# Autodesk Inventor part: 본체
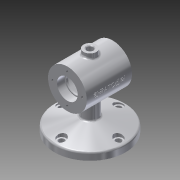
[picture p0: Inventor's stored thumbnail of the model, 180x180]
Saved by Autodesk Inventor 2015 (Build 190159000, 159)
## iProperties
Created: 2018-12
Part Number: 본체
Material: 알루미늄 6061
Document SubType Name: Modeling
Designer: now
Density: 2.7 g/cm^3
Appearance: 알루미늄 - 평지
Mass: 685.366 g
Surface Area: 556.634 cm^2
Volume: 253.839 cm^3
Author: now
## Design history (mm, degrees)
sketch "스케치1"
  geometry: C1 r 55 at (0, 0); 1 further point
  constraints: 1 centre point, 1 coincident
  dimensions: "d0" = 110 diameter of C1
extrude "돌출1" new body sketch "스케치1" distance "d1" = 11; taper "d2" = 0 deg
sketch "스케치2"
  geometry: C1 r 55 at (0, 0) reference; C2 r 12 at (0, 0)
  constraints: 1 centre point, 1 coincident
  dimensions: "d3" = 24 diameter of C2
extrude "돌출2" join sketch "스케치2" distance "d4" = 75; taper "d5" = 0 deg
sketch "스케치3"
  geometry: L1 (-55, 0)-(-55, 11) reference; L2 (-55, 11)-(-12, 11) reference; L3 (-12, 11)-(-12, 86) reference; L4 (-12, 86)-(12, 86) reference; L5 (12, 86)-(12, 11) reference; L6 (12, 11)-(55, 11) reference; L7 (55, 11)-(55, 0) reference; L8 (55, 0)-(-55, 0) reference; L9 (55, 11)-(12, 22.522); L10 (12, 22.522)-(0, 22.522); L11 (0, 22.522)-(0, 11); L12 (55, 11)-(-55, 11) reference; L13 (12, 11)-(55, 11); L14 (12, 11)-(0, 11); 1 further point
  constraints: 10 end point, 3 horizontal, 1 midpoint, 1 point on line
  dimensions: "d6" = 75 deg angle of L7 L9
revolve "회전1" sketch "스케치3" stored, may be unused: angle "d7" = 90 deg
fillet "모깎기1" dims "d8" = 3
sketch "스케치5"
  geometry: L1 (-52.776, 11.596)-(-12, 22.522) reference; L2 (-12, 22.522)-(-12, 86) reference; L3 (-12, 86)-(12, 86) reference; L4 (12, 86)-(12, 22.522) reference; L5 (12, 22.522)-(52.776, 11.596) reference; L6 (55, 8.698)-(55, 0) reference; L7 (55, 0)-(-55, 0) reference; L8 (-55, 0)-(-55, 8.698) reference; C1 r 30 at (0, 75); A1 r 3 centre (-52, 8.698) between (-52.776, 11.596) and (-55, 8.698) reference; A2 r 3 centre (52, 8.698) between (55, 8.698) and (52.776, 11.596) reference; 3 further points
  constraints: 1 centre point, 1 coincident, 1 midpoint, 1 vertical alignment
  dimensions: "d9" = 75 distance from line of L7 point (0, 75); "d10" = 60 diameter of C1
extrude "돌출3" join sketch "스케치5" stored distance "d11" = 70; taper "d12" = 0 deg
sketch "스케치6"
  geometry: C1 r 30 at (0, 0) reference; 1 further point
hole "구멍1" sketch "스케치6" at (0, 0) diameter "d13" = 28; stored, may be unused: countersink angle "d17" = 90 deg, drill point angle "d19" = 0 deg; dims "d14" = 6, "d15" = 32, "d16" = 12, "d18" = 15
sketch "스케치7"
  geometry: C1 r 14 at (0, 0) reference; 1 further point
hole "구멍2" sketch "스케치7" at (0, 0) diameter "d20" = 50; stored, may be unused: countersink angle "d24" = 90 deg, drill point angle "d26" = 0 deg; dims "d21" = 6, "d22" = 32, "d23" = 12, "d25" = 40
fillet "모깎기2" dims "d27" = 0.3
sketch "스케치8"
  geometry: C1 r 16 at (0, 0) reference; 2 further points
  constraints: 1 vertical alignment
  dimensions: "d28" = 23 distance of C1.centre point (0, 23)
hole "구멍3" sketch "스케치8" at (0, 23) diameter "d29" = 3.242; stored, may be unused: countersink angle "d33" = 90 deg, drill point angle "d35" = 118 deg; dims "d30" = 8, "d31" = 32, "d32" = 12, "d34" = 10
fillet "모깎기3" dims "d39" = 3
node "작업 평면1"
sketch "스케치9"
  geometry: L1 (-30, -35)-(30, -35) reference; C1 r 10 at (0, 0); 1 further point
  constraints: 1 centre point, 1 coincident
  dimensions: "d41" = 35 distance from line of C1.centre L1; "d42" = 20 diameter of C1
extrude "돌출4" join sketch "스케치9" stored distance "d43" = 70; taper "d44" = 0 deg
sketch "스케치10"
  geometry: C1 r 10 at (0, 0) reference
hole "구멍4" sketch "스케치10" at (0, 0) diameter "d45" = 10; stored, may be unused: countersink angle "d49" = 90 deg, drill point angle "d51" = 0 deg; dims "d46" = 8, "d47" = 32, "d48" = 12, "d50" = 10
chamfer "모따기1" distance "d52" = 1; stored, may be unused: second distance "d53" = 2, angle "d54" = 45 deg
sketch "스케치11" dims "d55" = 88
  geometry: C1 r 55 at (0, 0) reference; C2 r 4.5 at (-44, 0); 1 further point
  constraints: 2 horizontal alignment, 1 centre point, 1 coincident, 2 other
  dimensions: "d56" = 9 diameter of C2
extrude "돌출5" cut sketch "스케치11" distance "d57" = 10; taper "d58" = 0 deg
sketch "스케치12"
  geometry: C1 r 4.5 at (0, 0) reference; C2 r 7 at (0, 0); 1 further point
  constraints: 1 centre point, 1 coincident
  dimensions: "d59" = 14 diameter of C2
extrude "돌출6" cut sketch "스케치12" stored distance "d60" = 10; taper "d61" = 0 deg
fillet "모깎기4" dims "d65" = 3
fillet "모깎기5" dims "d66" = 3
node "작업 평면2"
sketch "스케치13" dims "d1" = 11, "d2" = 0, "d8" = 3
  geometry: L1 (-35, 105)-(-35, 45) reference; 2 further points
  constraints: 1 other
  dimensions: "d68" = 35 distance from line of L1 point (0, 75); "d69" = 30 vertical distance of L1.start point (0, 75)
feature "엠보싱1" sketch "스케치13" dims "d1" = 11, "d2" = 0, "d8" = 3, "d70" = 0.5, "d71" = 0
node "솔리드1"
mirror "대칭1"
pattern_circular "원형 패턴1" dims angle "d37" = 360 deg
mirror "대칭2"
pattern_circular "원형 패턴2" dims angle "d63" = 360 deg
node "절단 모서리 투영1"
node "절단 모서리 투영3"
other parameters: "d40" = 112, "d67" = 70.75
